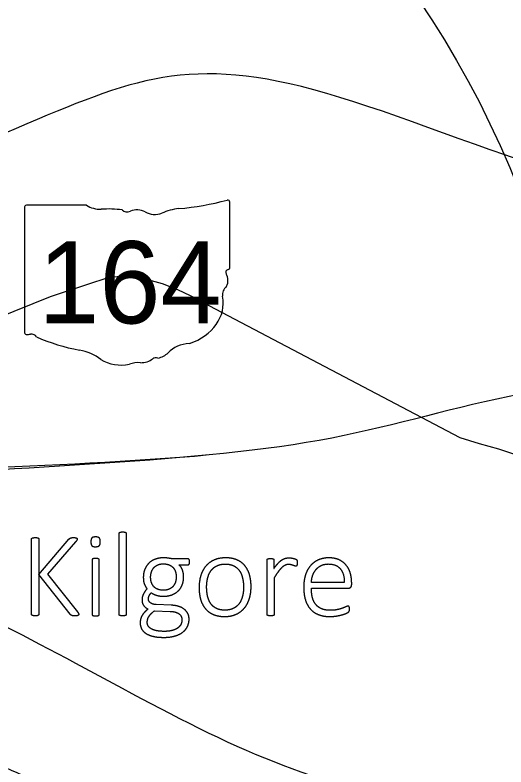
# Model space of a CAD drawing. Extents: x -202 to 1556, y 0 to 676.
# Drawn here: x 227.8 to 272.6, y 308.6 to 377.2 of the extents above; entities that cross this region are included whole.
import ezdxf

# ---------------------------------------------------------------- set-up
doc = ezdxf.new("R2010")
doc.units = 0
for name, color, linetype in [('Default', 7, 'Continuous'), ('GM_X_City_Street', 7, 'Continuous'), ('SH_Data', 7, 'Continuous')]:
    doc.layers.add(name, color=color, linetype=linetype)

msp = doc.modelspace()

# ---------------------------------------------------------------- linework, layer by layer
at = {"layer": 'Default'}
for p, q in [((229.272, 322.49), (229.272, 329.347)), ((237.268, 322.49), (237.268, 329.861)), ((237.922, 329.861), (237.922, 322.49)), ((235.546, 329.105), (235.546, 329.105)), ((234.798, 327.438), (234.798, 322.49)), ((235.452, 322.49), (235.452, 327.438)), ((243.527, 327.554), (242.068, 327.554)), ((243.702, 327.274), (243.702, 327.274)), ((250.776, 322.49), (250.776, 327.438)), ((251.397, 327.438), (251.397, 326.656)), ((253.519, 327.186), (253.519, 327.186)), ((242.745, 327), (243.527, 327)), ((242.48, 325.897), (242.48, 325.897)), ((251.43, 325.836), (251.43, 322.49)), ((257.824, 325.405), (254.821, 325.405)), ((258.498, 325.216), (258.498, 325.347)), ((248.627, 324.957), (248.627, 324.957)), ((249.315, 325.016), (249.315, 325.016)), ((254.821, 324.871), (258.192, 324.871)), ((242.005, 323.321), (240.662, 323.376)), ((233.584, 322.501), (233.584, 322.501)), ((240.488, 322.809), (241.925, 322.759)), ((243.001, 321.999), (243.001, 321.999))]:
    msp.add_line(p, q, dxfattribs=at)
for points in [[(273.562, 337.017), (271.919, 337.55), (270.182, 338.04), (268.402, 338.583), (244.919, 350.933), (244.35, 351.272), (242.625, 352.088), (241.233, 352.641), (239.899, 353.009), (238.772, 353.251), (237.714, 353.292), (236.464, 353.229), (234.919, 352.768), (230.985, 351.438), (226.027, 349.48), (217.09, 345.584), (202.181, 338.671), (199.387, 337.604), (198.408, 337.407), (197.383, 337.312), (196.175, 337.262), (189.768, 337.477)], [(229.94, 329.347), (229.94, 326.132), (232.683, 329.347)], [(233.299, 329.101), (230.721, 326.154), (233.474, 322.703)], [(232.803, 322.49), (229.94, 326.121), (229.94, 322.49)]]:
    msp.add_lwpolyline(points, dxfattribs=at)
for points in [[(237.268, 329.861), (237.268, 329.894), (237.282, 329.921)], [(237.282, 329.921), (237.295, 329.949), (237.334, 329.968)], [(237.334, 329.968), (237.372, 329.987), (237.435, 329.995)], [(237.435, 329.995), (237.499, 330.003), (237.592, 330.003)], [(237.592, 330.003), (237.691, 330.003), (237.754, 329.995)], [(237.754, 329.995), (237.818, 329.987), (237.853, 329.968)], [(237.853, 329.968), (237.889, 329.949), (237.905, 329.921)], [(237.905, 329.921), (237.922, 329.894), (237.922, 329.861)], [(229.272, 329.347), (229.272, 329.38), (229.289, 329.407)], [(229.289, 329.407), (229.305, 329.435), (229.343, 329.451)], [(229.343, 329.451), (229.382, 329.467), (229.447, 329.478)], [(229.447, 329.478), (229.513, 329.489), (229.606, 329.489)], [(229.606, 329.489), (229.704, 329.489), (229.767, 329.478)], [(229.767, 329.478), (229.83, 329.467), (229.869, 329.451)], [(229.869, 329.451), (229.907, 329.435), (229.923, 329.407)], [(229.923, 329.407), (229.94, 329.38), (229.94, 329.347)], [(232.683, 329.347), (232.715, 329.385), (232.754, 329.413)], [(232.754, 329.413), (232.792, 329.44), (232.841, 329.457)], [(232.841, 329.457), (232.89, 329.473), (232.956, 329.481)], [(232.956, 329.481), (233.021, 329.489), (233.119, 329.489)], [(233.119, 329.489), (233.217, 329.489), (233.277, 329.478)], [(233.277, 329.478), (233.338, 329.467), (233.373, 329.448)], [(233.4, 329.232), (233.37, 329.178), (233.299, 329.101)], [(233.373, 329.448), (233.408, 329.429), (233.419, 329.405)], [(233.43, 329.347), (233.43, 329.287), (233.4, 329.232)], [(233.419, 329.405), (233.43, 329.38), (233.43, 329.347)], [(234.785, 329.456), (234.692, 329.363), (234.692, 329.1)], [(235.124, 329.549), (234.878, 329.549), (234.785, 329.456)], [(235.456, 329.459), (235.365, 329.549), (235.124, 329.549)], [(235.546, 329.105), (235.546, 329.368), (235.456, 329.459)], [(234.692, 329.1), (234.692, 328.836), (234.782, 328.746)], [(234.782, 328.746), (234.872, 328.655), (235.113, 328.655)], [(235.113, 328.655), (235.36, 328.655), (235.453, 328.748)], [(235.453, 328.748), (235.546, 328.842), (235.546, 329.105)], [(234.812, 327.499), (234.798, 327.471), (234.798, 327.438)], [(234.864, 327.545), (234.826, 327.526), (234.812, 327.499)], [(234.966, 327.572), (234.903, 327.564), (234.864, 327.545)], [(235.123, 327.581), (235.029, 327.581), (234.966, 327.572)], [(235.285, 327.572), (235.222, 327.581), (235.123, 327.581)], [(235.384, 327.545), (235.348, 327.564), (235.285, 327.572)], [(235.436, 327.499), (235.42, 327.526), (235.384, 327.545)], [(235.452, 327.438), (235.452, 327.471), (235.436, 327.499)], [(239.993, 327.165), (239.75, 326.935), (239.614, 326.605)], [(240.576, 327.518), (240.237, 327.395), (239.993, 327.165)], [(241.319, 327.641), (240.914, 327.641), (240.576, 327.518)], [(241.721, 327.616), (241.532, 327.641), (241.319, 327.641)], [(242.068, 327.554), (241.909, 327.592), (241.721, 327.616)], [(243.661, 327.483), (243.62, 327.554), (243.527, 327.554)], [(243.652, 327.06), (243.702, 327.121), (243.702, 327.274)], [(243.702, 327.274), (243.702, 327.411), (243.661, 327.483)], [(245.931, 327.438), (245.477, 327.236), (245.173, 326.872)], [(246.991, 327.641), (246.384, 327.641), (245.931, 327.438)], [(248.005, 327.46), (247.571, 327.641), (246.991, 327.641)], [(248.73, 326.938), (248.44, 327.28), (248.005, 327.46)], [(250.776, 327.438), (250.776, 327.471), (250.79, 327.499)], [(250.79, 327.499), (250.804, 327.526), (250.842, 327.545)], [(250.842, 327.545), (250.881, 327.564), (250.938, 327.572)], [(250.938, 327.572), (250.996, 327.581), (251.09, 327.581)], [(251.09, 327.581), (251.183, 327.581), (251.243, 327.572)], [(251.243, 327.572), (251.304, 327.564), (251.337, 327.545)], [(251.337, 327.545), (251.37, 327.526), (251.384, 327.499)], [(251.384, 327.499), (251.397, 327.471), (251.397, 327.438)], [(251.397, 326.656), (251.61, 326.968), (251.79, 327.159)], [(251.79, 327.159), (251.97, 327.351), (252.134, 327.457)], [(252.134, 327.457), (252.297, 327.564), (252.453, 327.602)], [(252.453, 327.602), (252.608, 327.641), (252.772, 327.641)], [(252.772, 327.641), (252.843, 327.641), (252.936, 327.632)], [(252.936, 327.632), (253.028, 327.624), (253.135, 327.602)], [(253.135, 327.602), (253.241, 327.58), (253.326, 327.55)], [(253.326, 327.55), (253.41, 327.52), (253.443, 327.496)], [(253.443, 327.496), (253.476, 327.471), (253.487, 327.452)], [(253.487, 327.452), (253.498, 327.433), (253.506, 327.403)], [(253.506, 327.403), (253.514, 327.372), (253.517, 327.321)], [(253.519, 327.186), (253.519, 327.104), (253.514, 327.047)], [(253.517, 327.321), (253.519, 327.269), (253.519, 327.186)], [(255.467, 327.457), (255.044, 327.274), (254.743, 326.927)], [(256.41, 327.641), (255.891, 327.641), (255.467, 327.457)], [(257.361, 327.455), (256.968, 327.641), (256.41, 327.641)], [(258.009, 326.954), (257.755, 327.268), (257.361, 327.455)], [(239.614, 326.605), (239.477, 326.274), (239.477, 325.859)], [(240.215, 326.334), (240.286, 326.558), (240.428, 326.727)], [(240.428, 326.727), (240.57, 326.897), (240.788, 326.995)], [(240.788, 326.995), (241.007, 327.093), (241.296, 327.093)], [(241.296, 327.093), (241.864, 327.093), (242.172, 326.776)], [(242.172, 326.776), (242.48, 326.46), (242.48, 325.897)], [(243.064, 326.489), (242.974, 326.765), (242.745, 327)], [(243.154, 325.908), (243.154, 326.213), (243.064, 326.489)], [(243.527, 327), (243.603, 327), (243.652, 327.06)], [(245.173, 326.872), (244.87, 326.509), (244.72, 326.011)], [(245.355, 325.81), (245.454, 326.193), (245.659, 326.475)], [(245.659, 326.475), (245.864, 326.756), (246.187, 326.915)], [(246.187, 326.915), (246.51, 327.073), (246.953, 327.073)], [(246.953, 327.073), (247.434, 327.073), (247.757, 326.901)], [(247.757, 326.901), (248.08, 326.729), (248.272, 326.436)], [(249.167, 326.11), (249.019, 326.596), (248.73, 326.938)], [(252.137, 326.768), (251.981, 326.629), (251.809, 326.399)], [(252.434, 326.97), (252.292, 326.908), (252.137, 326.768)], [(252.723, 327.033), (252.576, 327.033), (252.434, 326.97)], [(252.952, 327.009), (252.849, 327.033), (252.723, 327.033)], [(253.143, 326.957), (253.056, 326.984), (252.952, 327.009)], [(253.296, 326.905), (253.23, 326.929), (253.143, 326.957)], [(253.41, 326.88), (253.361, 326.88), (253.296, 326.905)], [(253.462, 326.899), (253.443, 326.88), (253.41, 326.88)], [(253.495, 326.954), (253.481, 326.918), (253.462, 326.899)], [(253.514, 327.047), (253.508, 326.99), (253.495, 326.954)], [(254.743, 326.927), (254.442, 326.58), (254.281, 326.082)], [(254.941, 326.037), (255.045, 326.341), (255.239, 326.571)], [(255.239, 326.571), (255.432, 326.801), (255.714, 326.94)], [(255.714, 326.94), (255.995, 327.08), (256.366, 327.08)], [(256.366, 327.08), (257.087, 327.08), (257.464, 326.637)], [(257.464, 326.637), (257.841, 326.193), (257.824, 325.405)], [(258.381, 326.223), (258.263, 326.639), (258.009, 326.954)], [(239.477, 325.859), (239.477, 325.514), (239.564, 325.268)], [(240.144, 325.859), (240.144, 326.11), (240.215, 326.334)], [(240.453, 324.998), (240.144, 325.312), (240.144, 325.859)], [(242.48, 325.897), (242.48, 325.656), (242.409, 325.435)], [(243.021, 325.159), (243.154, 325.487), (243.154, 325.908)], [(244.72, 326.011), (244.569, 325.514), (244.569, 324.923)], [(245.257, 324.985), (245.257, 325.428), (245.355, 325.81)], [(248.272, 326.436), (248.463, 326.144), (248.545, 325.761)], [(249.315, 325.016), (249.315, 325.623), (249.167, 326.11)], [(251.809, 326.399), (251.638, 326.17), (251.43, 325.836)], [(254.281, 326.082), (254.12, 325.585), (254.12, 324.956)], [(254.821, 325.405), (254.837, 325.733), (254.941, 326.037)], [(258.498, 325.347), (258.498, 325.807), (258.381, 326.223)], [(239.564, 325.268), (239.652, 325.022), (239.81, 324.815)], [(242.409, 325.435), (242.338, 325.214), (242.197, 325.047)], [(242.641, 324.604), (242.887, 324.831), (243.021, 325.159)], [(248.545, 325.761), (248.627, 325.378), (248.627, 324.957)], [(258.394, 324.945), (258.498, 325.019), (258.498, 325.216)], [(239.81, 324.815), (239.622, 324.607), (239.49, 324.347)], [(240.018, 324.208), (240.091, 324.35), (240.204, 324.459)], [(240.204, 324.459), (240.373, 324.323), (240.674, 324.23)], [(241.318, 324.684), (240.761, 324.684), (240.453, 324.998)], [(241.834, 324.782), (241.613, 324.684), (241.318, 324.684)], [(242.197, 325.047), (242.055, 324.881), (241.834, 324.782)], [(242.056, 324.257), (242.395, 324.377), (242.641, 324.604)], [(244.569, 324.923), (244.569, 324.311), (244.714, 323.824)], [(245.339, 324.173), (245.257, 324.558), (245.257, 324.985)], [(248.627, 324.957), (248.627, 324.509), (248.529, 324.126)], [(249.162, 323.928), (249.315, 324.426), (249.315, 325.016)], [(254.12, 324.956), (254.12, 324.3), (254.276, 323.802)], [(254.911, 324.041), (254.821, 324.412), (254.821, 324.871)], [(258.192, 324.871), (258.291, 324.871), (258.394, 324.945)], [(239.49, 324.347), (239.357, 324.087), (239.357, 323.748)], [(239.357, 323.748), (239.357, 323.519), (239.489, 323.316)], [(239.944, 323.879), (239.944, 324.065), (240.018, 324.208)], [(240.144, 323.529), (239.944, 323.671), (239.944, 323.879)], [(240.674, 324.23), (240.974, 324.137), (241.307, 324.137)], [(241.307, 324.137), (241.717, 324.137), (242.056, 324.257)], [(244.714, 323.824), (244.859, 323.338), (245.152, 322.996)], [(245.612, 323.497), (245.421, 323.787), (245.339, 324.173)], [(248.529, 324.126), (248.43, 323.743), (248.225, 323.465)], [(248.705, 323.064), (249.008, 323.431), (249.162, 323.928)], [(254.276, 323.802), (254.431, 323.305), (254.732, 322.969)], [(255.209, 323.404), (255.001, 323.669), (254.911, 324.041)], [(239.489, 323.316), (239.621, 323.114), (239.901, 322.972)], [(240.662, 323.376), (240.344, 323.387), (240.144, 323.529)], [(242.644, 323.228), (242.345, 323.31), (242.005, 323.321)], [(243.167, 322.985), (242.942, 323.146), (242.644, 323.228)], [(246.127, 323.038), (245.804, 323.208), (245.612, 323.497)], [(248.225, 323.465), (248.02, 323.186), (247.697, 323.027)], [(247.948, 322.493), (248.402, 322.698), (248.705, 323.064)], [(255.749, 322.997), (255.416, 323.139), (255.209, 323.404)], [(257.658, 323.049), (257.458, 322.975), (257.185, 322.915)], [(257.985, 323.182), (257.857, 323.122), (257.658, 323.049)], [(258.168, 323.242), (258.114, 323.242), (257.985, 323.182)], [(258.228, 323.226), (258.201, 323.242), (258.168, 323.242)], [(258.272, 323.174), (258.256, 323.21), (258.228, 323.226)], [(258.297, 323.084), (258.288, 323.138), (258.272, 323.174)], [(258.305, 322.947), (258.305, 323.029), (258.297, 323.084)], [(229.289, 322.43), (229.272, 322.457), (229.272, 322.49)], [(229.343, 322.386), (229.305, 322.403), (229.289, 322.43)], [(229.447, 322.359), (229.382, 322.37), (229.343, 322.386)], [(229.606, 322.348), (229.513, 322.348), (229.447, 322.359)], [(229.767, 322.359), (229.704, 322.348), (229.606, 322.348)], [(229.869, 322.386), (229.83, 322.37), (229.767, 322.359)], [(229.923, 322.43), (229.907, 322.403), (229.869, 322.386)], [(229.94, 322.49), (229.94, 322.457), (229.923, 322.43)], [(232.896, 322.405), (232.841, 322.441), (232.803, 322.49)], [(233.051, 322.359), (232.95, 322.37), (232.896, 322.405)], [(233.251, 322.348), (233.152, 322.348), (233.051, 322.359)], [(233.42, 322.359), (233.354, 322.348), (233.251, 322.348)], [(233.524, 322.389), (233.485, 322.37), (233.42, 322.359)], [(233.474, 322.703), (233.551, 322.605), (233.567, 322.567)], [(233.573, 322.436), (233.562, 322.408), (233.524, 322.389)], [(233.567, 322.567), (233.584, 322.528), (233.584, 322.501)], [(233.584, 322.501), (233.584, 322.463), (233.573, 322.436)], [(234.798, 322.49), (234.798, 322.457), (234.812, 322.43)], [(234.812, 322.43), (234.826, 322.403), (234.864, 322.386)], [(234.864, 322.386), (234.903, 322.37), (234.966, 322.359)], [(234.966, 322.359), (235.029, 322.348), (235.123, 322.348)], [(235.123, 322.348), (235.222, 322.348), (235.285, 322.359)], [(235.285, 322.359), (235.348, 322.37), (235.384, 322.386)], [(235.384, 322.386), (235.42, 322.403), (235.436, 322.43)], [(235.436, 322.43), (235.452, 322.457), (235.452, 322.49)], [(237.282, 322.43), (237.268, 322.457), (237.268, 322.49)], [(237.334, 322.386), (237.295, 322.403), (237.282, 322.43)], [(237.435, 322.359), (237.372, 322.37), (237.334, 322.386)], [(237.592, 322.348), (237.499, 322.348), (237.435, 322.359)], [(237.754, 322.359), (237.691, 322.348), (237.592, 322.348)], [(237.853, 322.386), (237.818, 322.37), (237.754, 322.359)], [(237.905, 322.43), (237.889, 322.403), (237.853, 322.386)], [(237.922, 322.49), (237.922, 322.457), (237.905, 322.43)], [(239.368, 322.387), (239.277, 322.234), (239.234, 322.064)], [(239.592, 322.682), (239.458, 322.54), (239.368, 322.387)], [(239.901, 322.972), (239.726, 322.824), (239.592, 322.682)], [(239.966, 322.254), (240.04, 322.382), (240.165, 322.519)], [(240.165, 322.519), (240.291, 322.655), (240.488, 322.809)], [(241.925, 322.759), (242.416, 322.743), (242.709, 322.552)], [(242.709, 322.552), (243.001, 322.36), (243.001, 321.999)], [(243.523, 322.589), (243.392, 322.824), (243.167, 322.985)], [(243.655, 322.037), (243.655, 322.354), (243.523, 322.589)], [(245.152, 322.996), (245.444, 322.654), (245.879, 322.471)], [(245.879, 322.471), (246.313, 322.288), (246.893, 322.288)], [(246.931, 322.869), (246.45, 322.869), (246.127, 323.038)], [(246.893, 322.288), (247.494, 322.288), (247.948, 322.493)], [(247.697, 323.027), (247.374, 322.869), (246.931, 322.869)], [(250.79, 322.43), (250.776, 322.457), (250.776, 322.49)], [(250.842, 322.386), (250.804, 322.403), (250.79, 322.43)], [(250.944, 322.359), (250.881, 322.37), (250.842, 322.386)], [(251.101, 322.348), (251.007, 322.348), (250.944, 322.359)], [(251.263, 322.359), (251.199, 322.348), (251.101, 322.348)], [(251.362, 322.386), (251.326, 322.37), (251.263, 322.359)], [(251.414, 322.43), (251.397, 322.403), (251.362, 322.386)], [(251.43, 322.49), (251.43, 322.457), (251.414, 322.43)], [(254.732, 322.969), (255.032, 322.632), (255.475, 322.46)], [(255.475, 322.46), (255.917, 322.288), (256.491, 322.288)], [(256.568, 322.855), (256.082, 322.855), (255.749, 322.997)], [(257.185, 322.915), (256.912, 322.855), (256.568, 322.855)], [(257.144, 322.342), (257.447, 322.397), (257.676, 322.465)], [(257.676, 322.465), (257.906, 322.532), (258.048, 322.6)], [(258.048, 322.6), (258.19, 322.668), (258.217, 322.696)], [(258.217, 322.696), (258.245, 322.723), (258.261, 322.75)], [(258.261, 322.75), (258.277, 322.778), (258.286, 322.808)], [(258.286, 322.808), (258.294, 322.838), (258.299, 322.873)], [(258.299, 322.873), (258.305, 322.909), (258.305, 322.947)], [(239.234, 322.064), (239.19, 321.895), (239.19, 321.703)], [(239.19, 321.703), (239.19, 321.425), (239.308, 321.184)], [(239.837, 321.753), (239.837, 321.879), (239.865, 322.002)], [(240.244, 321.141), (239.837, 321.349), (239.837, 321.753)], [(239.865, 322.002), (239.892, 322.125), (239.966, 322.254)], [(243.001, 321.999), (243.001, 321.792), (242.919, 321.6)], [(243.521, 321.408), (243.655, 321.709), (243.655, 322.037)], [(256.491, 322.288), (256.841, 322.288), (257.144, 322.342)], [(239.308, 321.184), (239.425, 320.943), (239.685, 320.766)], [(241.378, 320.933), (240.652, 320.933), (240.244, 321.141)], [(242.146, 321.023), (241.837, 320.933), (241.378, 320.933)], [(242.646, 321.261), (242.455, 321.114), (242.146, 321.023)], [(242.919, 321.6), (242.837, 321.409), (242.646, 321.261)], [(243.105, 320.88), (243.387, 321.107), (243.521, 321.408)], [(239.685, 320.766), (239.945, 320.588), (240.353, 320.487)], [(240.353, 320.487), (240.76, 320.386), (241.34, 320.386)], [(241.34, 320.386), (241.948, 320.386), (242.385, 320.52)], [(242.385, 320.52), (242.823, 320.654), (243.105, 320.88)]]:
    msp.add_open_spline(points, degree=2, dxfattribs=at)
at = {"layer": 'GM_X_City_Street'}
for p, q in [((247.366, 354.129), (247.366, 360.084)), ((228.617, 359.606), (228.617, 348.221)), ((234.292, 359.802), (228.801, 359.802)), ((247.364, 354.13), (247.366, 354.129))]:
    msp.add_line(p, q, dxfattribs=at)
for centre, major_axis, start_param, end_param in [((240.687, 375.323), (19.884, 0), 4.814394, 5.042369), ((247.158, 360.109), (0.209, 0), 6.141152, 7.989035), ((228.831, 359.63), (0.217, 0), 1.712693, 3.28349), ((235.6, 361.124), (2.107, 0), 4.042523, 4.731795), ((236.298, 353.411), (7.564, 0), 1.404758, 1.657858), ((238.908, 358.374), (1.264, 0), 0.950623, 2.079405), ((243.223, 356.325), (4, 0), 1.699011, 2.107814), ((238.015, 359.689), (0.608, 0), 3.836095, 5.185415), ((240.539, 360.178), (1.52, 0), 4.081561, 5.145723), ((247.318, 353.691), (0.323, 0), 1.883978, 3.671073), ((247.143, 354.106), (0.223, 0), 5.05454, 6.418171), ((245.263, 352.939), (1.939, 0), 5.934695, 6.695948), ((248.114, 351.636), (1.411, 0), 2.387724, 3.262537), ((241.801, 350.879), (4.973, 0), 5.101752, 6.440018), ((228.833, 348.197), (0.219, 0), 3.00124, 4.508301), ((228.866, 349.361), (1.672, 0), 4.665946, 4.897461), ((229.209, 347.565), (0.603, 0), 0.519207, 1.627899), ((236.822, 357.793), (14.359, 0), 4.195997, 4.488961), ((243.898, 345.025), (2.724, 0), 1.647645, 2.488434), ((232.541, 343.107), (4.493, 0), 0.823519, 1.323587), ((237.4, 347.508), (2.851, 0), 4.026481, 4.996735), ((239.255, 346.656), (1.519, 0), 4.691044, 5.507374), ((240.629, 345.553), (0.428, 0), 1.147584, 2.315152), ((240.447, 347.118), (1.607, 0), 4.937069, 5.64225), ((239.047, 343.572), (2.342, 0), 1.495662, 1.94098)]:
    msp.add_ellipse(centre, major_axis=major_axis, ratio=0.8, start_param=start_param, end_param=end_param, dxfattribs=at)
at = {"layer": 'SH_Data'}
msp.add_circle((190, 328.22), 90, dxfattribs=at)
for points, degree in [([(290.038, 365.436), (291.676, 355.396), (249.472, 375.825), (233.911, 369.396), (203.271, 356.422), (192.616, 347.503)], 3), ([(296.55, 344.124), (275.7, 344.892), (260.185, 336.272), (208.963, 335.841), (193.502, 330.958), (191.477, 334.718)], 3), ([(296.55, 344.124), (275.7, 344.892), (260.185, 336.272), (208.963, 335.841), (194.183, 333.891), (191.658, 340.115)], 3), ([(327.874, 307.057), (327.874, 312.455), (319.069, 315.684), (299.388, 307.935), (261.96, 301.8), (211.627, 330.376), (195.439, 326.278), (192.616, 329.634)], 2), ([(281.763, 263.43), (274.751, 268.496), (283.527, 280.275), (254.721, 295.671), (211.15, 315.716), (198.849, 323.426)], 2)]:
    msp.add_open_spline(points, degree=degree, dxfattribs=at)

# ---------------------------------------------------------------- texts
at = {"layer": 'GM_X_City_Street'}
msp.add_text('164', height=7.5, dxfattribs=at).set_placement((229.885, 349.024))

doc.saveas('drawing.dxf')
